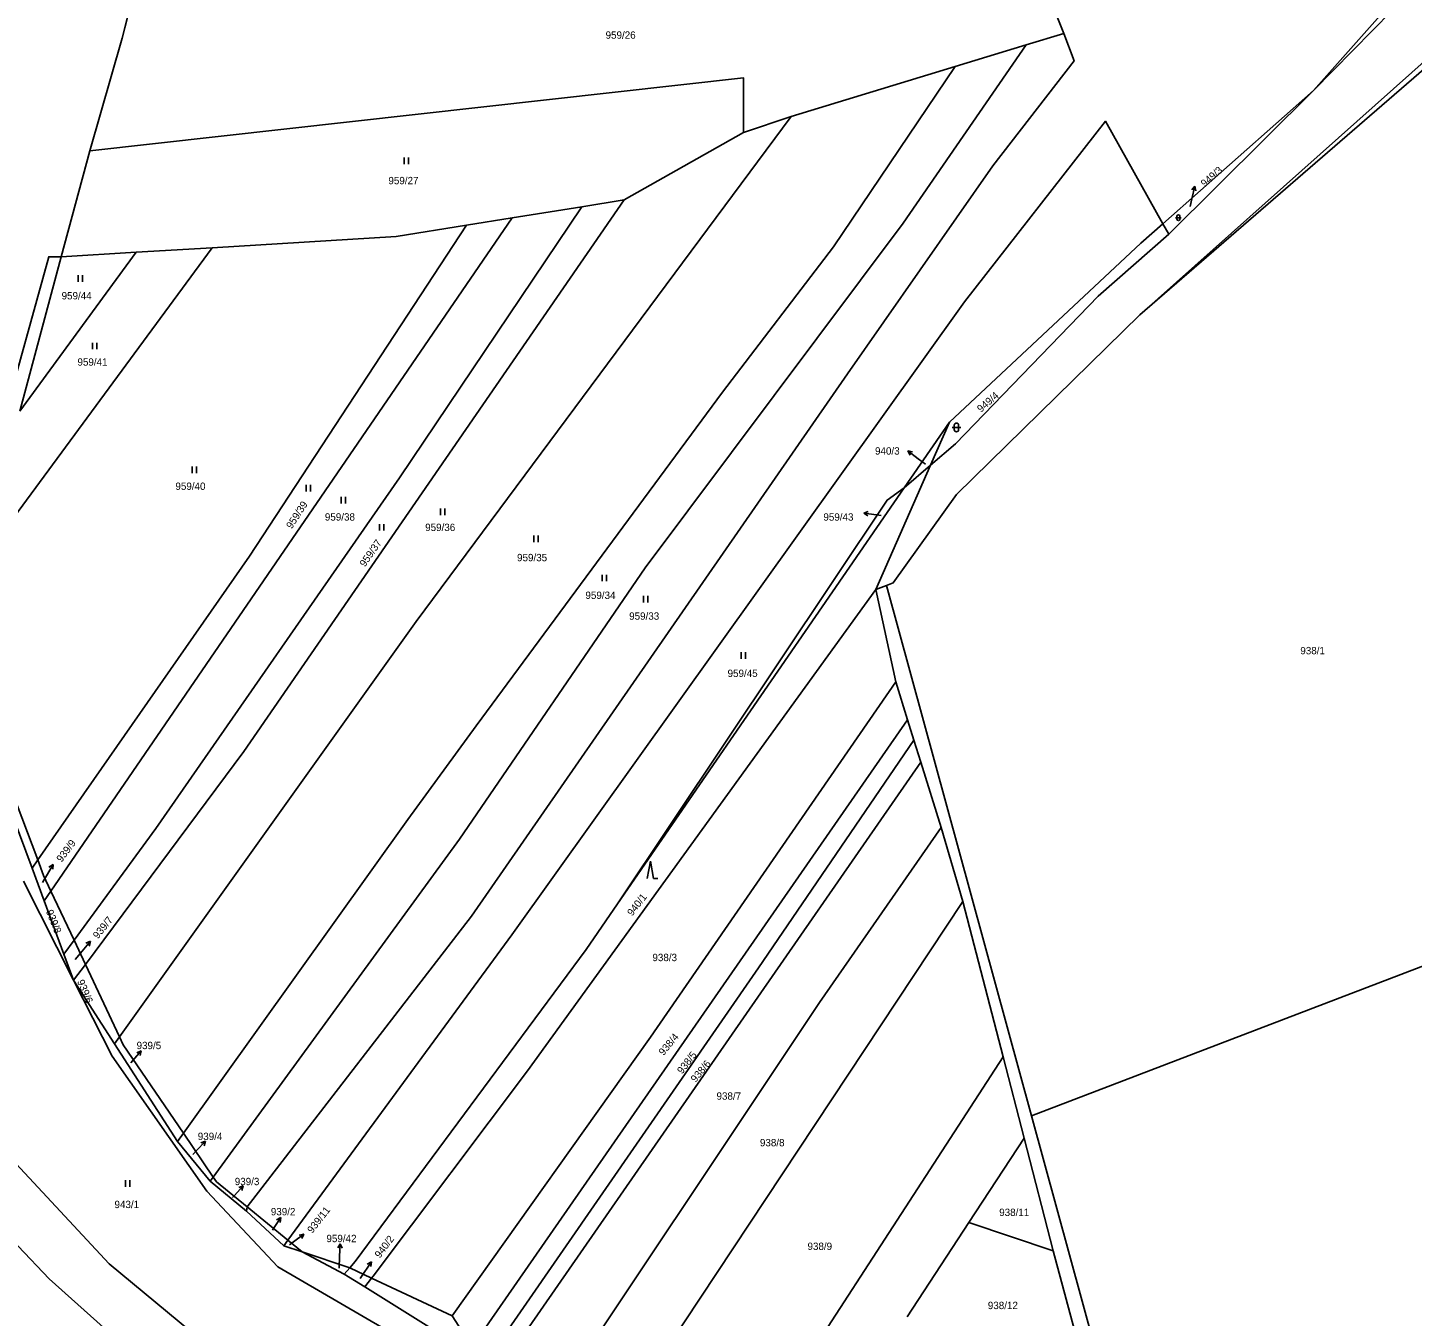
# Model space of a CAD drawing. Extents: x -757266 to -753360, y -1162585 to -1157740.
# Drawn here: x -756805.9 to -756485.7, y -1158661.2 to -1158363.2 of the extents above; entities that cross this region are included whole.
import ezdxf

# ---------------------------------------------------------------- set-up
doc = ezdxf.new("R2010")
doc.units = 0
for name, color, linetype in [('Hranice kat_území', 7, 'Continuous'), ('Hranice parcel', 7, 'Continuous'), ('Parcelní čísla', 7, 'Continuous'), ('Pop  PČ popisy', 7, 'Continuous'), ('Značky kultur', 7, 'Continuous')]:
    doc.layers.add(name, color=color, linetype=linetype)

msp = doc.modelspace()

# ---------------------------------------------------------------- linework, layer by layer
at = {"layer": 'Hranice kat_území'}
msp.add_lwpolyline([(-756781.24, -1158354.6), (-756784.03, -1158365.59), (-756791.53, -1158391.65), (-756798.13, -1158416.19), (-756801.03, -1158416.15), (-756811.68, -1158454.87), (-756825.92, -1158504.48), (-756835.2, -1158536), (-756846.27, -1158568.28), (-756847.94, -1158578.11), (-756854.12, -1158598.67), (-756855.85, -1158604.43), (-756860.92, -1158621.3), (-756876.64, -1158666.26), (-756892.84, -1158710.67), (-756909.75, -1158755.31), (-756929.5, -1158803.77), (-756945.9, -1158844.06)], dxfattribs=at)
at = {"layer": 'Hranice parcel'}
for p, q in [((-756566.33, -1158364.49), (-756578.91, -1158333.04)), ((-756548.7, -1158429.59), (-756447.67, -1158342.08)), ((-756781.24, -1158354.6), (-756784.03, -1158365.59)), ((-756491.3, -1158358.26), (-756508.58, -1158377.69)), ((-756490.34, -1158359.21), (-756508.58, -1158377.69)), ((-756574.98, -1158367.13), (-756566.33, -1158364.49)), ((-756784.03, -1158365.59), (-756791.53, -1158391.65)), ((-756591.46, -1158372.16), (-756574.98, -1158367.13)), ((-756629.34, -1158383.73), (-756591.46, -1158372.16)), ((-756508.58, -1158377.69), (-756543.38, -1158408.52)), ((-756508.58, -1158377.69), (-756542.03, -1158410.93)), ((-756640.34, -1158387.4), (-756629.34, -1158383.73)), ((-756667.96, -1158403.01), (-756640.34, -1158387.4)), ((-756791.53, -1158391.65), (-756798.13, -1158416.19)), ((-756677.78, -1158404.58), (-756667.96, -1158403.01)), ((-756693.84, -1158407.15), (-756677.78, -1158404.58)), ((-756704.46, -1158408.85), (-756693.84, -1158407.15)), ((-756543.38, -1158408.52), (-756542.03, -1158410.93)), ((-756763.27, -1158414.06), (-756817.31, -1158487.51)), ((-756780.81, -1158415.13), (-756807.73, -1158451.88)), ((-756807.73, -1158451.88), (-756798.13, -1158416.19)), ((-756798.13, -1158416.19), (-756801.03, -1158416.15)), ((-756798.13, -1158416.19), (-756780.81, -1158415.13)), ((-756780.81, -1158415.13), (-756763.27, -1158414.06)), ((-756592.73, -1158454.42), (-756603.18, -1158469.59)), ((-756597.1, -1158464.34), (-756592.73, -1158454.42)), ((-756609.77, -1158493.12), (-756597.1, -1158464.34)), ((-756597.1, -1158464.34), (-756603.18, -1158469.59)), ((-756603.18, -1158469.59), (-756669.5, -1158565.82)), ((-756607.32, -1158492.2), (-756609.77, -1158493.12)), ((-756605.18, -1158514.49), (-756609.77, -1158493.12)), ((-756607.32, -1158492.2), (-756573.78, -1158614.85)), ((-756602.46, -1158523.21), (-756605.18, -1158514.49)), ((-756703.1, -1158668.26), (-756602.46, -1158523.21)), ((-756600.97, -1158527.97), (-756602.46, -1158523.21)), ((-756599.39, -1158533.04), (-756600.97, -1158527.97)), ((-756698.31, -1158675.71), (-756599.39, -1158533.04)), ((-756594.68, -1158548.12), (-756599.39, -1158533.04)), ((-756589.63, -1158565.22), (-756594.68, -1158548.12)), ((-756803.58, -1158555.65), (-756804.89, -1158557.54)), ((-756573.78, -1158614.85), (-756418.09, -1158555.21)), ((-756795.26, -1158583.48), (-756806.89, -1158560.55)), ((-756804.89, -1158557.54), (-756802.08, -1158565.11)), ((-756800.53, -1158562.84), (-756802.08, -1158565.11)), ((-756795.17, -1158574.23), (-756800.53, -1158562.84)), ((-756802.08, -1158565.11), (-756797.51, -1158577.42)), ((-756682.2, -1158705.02), (-756589.63, -1158565.22)), ((-756580.35, -1158601.17), (-756589.63, -1158565.22)), ((-756795.17, -1158574.23), (-756797.51, -1158577.42)), ((-756792.54, -1158579.83), (-756795.17, -1158574.23)), ((-756797.51, -1158577.42), (-756795.26, -1158583.48)), ((-756792.54, -1158579.83), (-756795.26, -1158583.48)), ((-756784.66, -1158596.58), (-756792.54, -1158579.83)), ((-756785.82, -1158598.21), (-756795.26, -1158583.48)), ((-756784.66, -1158596.58), (-756785.82, -1158598.21)), ((-756771.23, -1158620.76), (-756785.82, -1158598.21)), ((-756575.49, -1158619.99), (-756580.35, -1158601.17)), ((-756543.91, -1158724.09), (-756573.78, -1158614.85)), ((-756769.87, -1158618.85), (-756771.23, -1158620.76)), ((-756763.66, -1158629.91), (-756771.23, -1158620.76)), ((-756762.98, -1158628.97), (-756769.87, -1158618.85)), ((-756588.24, -1158639.46), (-756575.49, -1158619.99)), ((-756568.76, -1158646.08), (-756575.49, -1158619.99)), ((-756762.98, -1158628.97), (-756763.66, -1158629.91)), ((-756755.3, -1158636.87), (-756763.66, -1158629.91)), ((-756755.11, -1158635.9), (-756755.3, -1158636.87)), ((-756746.69, -1158644.89), (-756755.3, -1158636.87)), ((-756745.73, -1158643.58), (-756755.11, -1158635.9)), ((-756602.54, -1158661.29), (-756588.24, -1158639.46)), ((-756588.24, -1158639.46), (-756568.76, -1158646.08)), ((-756746.69, -1158644.89), (-756745.73, -1158643.58)), ((-756742.41, -1158646.3), (-756745.73, -1158643.58)), ((-756742.41, -1158646.3), (-756746.69, -1158644.89)), ((-756731.41, -1158649.97), (-756742.41, -1158646.3)), ((-756742.41, -1158646.3), (-756732.68, -1158651.43)), ((-756559.23, -1158681.29), (-756568.76, -1158646.08)), ((-756731.41, -1158649.97), (-756732.68, -1158651.43)), ((-756731.41, -1158649.97), (-756726.36, -1158652.34)), ((-756732.68, -1158651.43), (-756727.91, -1158654.4)), ((-756727.91, -1158654.4), (-756726.36, -1158652.34)), ((-756707.71, -1158661.08), (-756726.36, -1158652.34)), ((-756703.1, -1158668.26), (-756707.71, -1158661.08))]:
    msp.add_line(p, q, dxfattribs=at)
for points in [[(-756447.67, -1158342.08), (-756448.37, -1158340.11), (-756548.7, -1158429.59)], [(-756566.33, -1158364.49), (-756563.9, -1158370.88), (-756582.68, -1158395.1), (-756616.3, -1158443.25)], [(-756574.98, -1158367.13), (-756603.41, -1158408.36), (-756663.1, -1158488.06), (-756706.06, -1158550.84), (-756762.98, -1158628.97)], [(-756791.53, -1158391.65), (-756640.34, -1158374.79), (-756640.34, -1158387.4)], [(-756591.46, -1158372.16), (-756619.59, -1158413.83), (-756645.25, -1158447.45), (-756702.2, -1158524.66), (-756717.99, -1158546.3), (-756769.87, -1158618.85)], [(-756629.34, -1158383.73), (-756716.04, -1158500.54), (-756784.66, -1158596.58)], [(-756745.73, -1158643.58), (-756693.91, -1158572.95), (-756589.28, -1158426.55), (-756556.65, -1158384.81), (-756543.38, -1158408.52)], [(-756667.96, -1158403.01), (-756755.93, -1158530.58), (-756792.54, -1158579.83)], [(-756677.78, -1158404.58), (-756719.91, -1158467.27), (-756776.27, -1158548.39), (-756795.17, -1158574.23)], [(-756704.46, -1158408.85), (-756754.58, -1158485.41), (-756803.58, -1158555.65)], [(-756693.84, -1158407.15), (-756732.41, -1158463.4), (-756800.53, -1158562.84)], [(-756763.27, -1158414.06), (-756720.72, -1158411.46), (-756704.46, -1158408.85)], [(-756543.38, -1158408.52), (-756548.5, -1158413.05), (-756592.73, -1158454.42)], [(-756542.03, -1158410.93), (-756558.36, -1158425.3), (-756591.36, -1158459.39), (-756597.1, -1158464.34)], [(-756801.03, -1158416.15), (-756811.68, -1158454.87), (-756825.92, -1158504.48), (-756835.2, -1158536)], [(-756548.7, -1158429.59), (-756591.1, -1158471.17), (-756605.74, -1158491.6), (-756607.32, -1158492.2)], [(-756616.3, -1158443.25), (-756703.28, -1158568.66), (-756755.11, -1158635.9)], [(-756603.18, -1158469.59), (-756607.15, -1158472.44), (-756669.5, -1158565.82)], [(-756726.36, -1158652.34), (-756726.04, -1158651.92), (-756690.28, -1158604.41), (-756648.3, -1158546.4), (-756609.77, -1158493.12)], [(-756820.94, -1158501.85), (-756821.89, -1158503.54), (-756820.99, -1158510.1), (-756822.73, -1158509.72), (-756804.89, -1158557.54)], [(-756803.58, -1158555.65), (-756812.24, -1158532.59), (-756819.92, -1158512.2), (-756820.94, -1158501.85)], [(-756707.71, -1158661.08), (-756661.91, -1158596.62), (-756605.18, -1158514.49)], [(-756700.41, -1158672.44), (-756636.9, -1158580.56), (-756600.97, -1158527.97)], [(-756689.77, -1158689.02), (-756622.77, -1158588.64), (-756594.68, -1158548.12)], [(-756800.53, -1158562.84), (-756802.24, -1158559.21), (-756803.58, -1158555.65)], [(-756669.5, -1158565.82), (-756676.78, -1158576.39), (-756730.13, -1158648.51), (-756731.41, -1158649.97)], [(-756712.37, -1158672.52), (-756713.76, -1158669.73), (-756748.02, -1158649.78), (-756764.47, -1158632.26), (-756786.37, -1158600.99), (-756795.26, -1158583.48)], [(-756670.96, -1158755.67), (-756686.13, -1158736.94), (-756696.64, -1158725.27), (-756713.94, -1158710.12), (-756748.83, -1158680.75), (-756787.06, -1158649.03), (-756808.66, -1158625.84), (-756835.58, -1158596.23), (-756844.34, -1158586.44)], [(-756704.1, -1158962.35), (-756694.65, -1158943.1), (-756668.85, -1158906.92), (-756664.23, -1158896.45), (-756658.19, -1158866.49), (-756660.27, -1158849.21), (-756665.64, -1158810.88), (-756675.54, -1158767.56), (-756690.59, -1158747.65), (-756703.99, -1158734.09), (-756739.28, -1158704.77), (-756778.11, -1158672.96), (-756800.91, -1158652.49), (-756808.06, -1158644.98), (-756837.14, -1158613.12), (-756852.08, -1158598.85), (-756854.12, -1158598.67)], [(-756769.87, -1158618.85), (-756783.81, -1158598.38), (-756784.66, -1158596.58)], [(-756668.48, -1158733.77), (-756649.15, -1158707.23), (-756580.35, -1158601.17)], [(-756755.11, -1158635.9), (-756762.24, -1158630.06), (-756762.98, -1158628.97)], [(-756727.91, -1158654.4), (-756709.44, -1158665.92), (-756666.01, -1158753.76), (-756648.09, -1158869.34)]]:
    msp.add_lwpolyline(points, dxfattribs=at)
at = {"layer": 'Pop  PČ popisy'}
for p, q in [((-756536.005, -1158399.826), (-756536.718, -1158400.689)), ((-756536.68, -1158402.75), (-756536.005, -1158399.826)), ((-756536.005, -1158399.826), (-756535.742, -1158400.914)), ((-756537.09, -1158404.56), (-756536.68, -1158402.75)), ((-756599.96, -1158462.86), (-756602.357, -1158461.054)), ((-756602.357, -1158461.054), (-756601.256, -1158461.257)), ((-756602.357, -1158461.054), (-756601.858, -1158462.057)), ((-756598.29, -1158464.11), (-756599.96, -1158462.86)), ((-756612.559, -1158475.474), (-756611.504, -1158475.099)), ((-756609.58, -1158475.84), (-756612.559, -1158475.474)), ((-756612.559, -1158475.474), (-756611.626, -1158476.093)), ((-756608.55, -1158475.96), (-756609.58, -1158475.84)), ((-756801.53, -1158559.29), (-756800.03, -1158556.691)), ((-756800.03, -1158556.691), (-756800.964, -1158557.308)), ((-756800.03, -1158556.691), (-756800.097, -1158557.809)), ((-756802.44, -1158560.85), (-756801.53, -1158559.29)), ((-756793.31, -1158576.76), (-756791.381, -1158574.461)), ((-756791.381, -1158574.461), (-756792.408, -1158574.906)), ((-756791.381, -1158574.461), (-756791.641, -1158575.55)), ((-756794.88, -1158578.65), (-756793.31, -1158576.76)), ((-756782.04, -1158602.56), (-756781.61, -1158602.06)), ((-756781.61, -1158602.06), (-756779.641, -1158599.795)), ((-756779.641, -1158599.795), (-756780.676, -1158600.222)), ((-756779.641, -1158599.795), (-756779.92, -1158600.879)), ((-756766.83, -1158622.87), (-756764.783, -1158620.675)), ((-756764.783, -1158620.675), (-756765.833, -1158621.066)), ((-756764.783, -1158620.675), (-756765.1, -1158621.749)), ((-756767.69, -1158623.78), (-756766.83, -1158622.87)), ((-756758.09, -1158633.21), (-756756.043, -1158631.015)), ((-756756.043, -1158631.015), (-756757.093, -1158631.406)), ((-756756.043, -1158631.015), (-756756.36, -1158632.089)), ((-756758.52, -1158633.68), (-756758.09, -1158633.21)), ((-756749.04, -1158640.85), (-756747.362, -1158638.362)), ((-756747.362, -1158638.362), (-756748.337, -1158638.912)), ((-756747.362, -1158638.362), (-756747.507, -1158639.472)), ((-756749.32, -1158641.27), (-756749.04, -1158640.85)), ((-756744.44, -1158643.98), (-756742.012, -1158642.216)), ((-756742.012, -1158642.216), (-756743.117, -1158642.4)), ((-756742.012, -1158642.216), (-756742.528, -1158643.21)), ((-756745.37, -1158644.65), (-756744.44, -1158643.98)), ((-756733.655, -1158644.391), (-756734.191, -1158645.374)), ((-756733.76, -1158647.39), (-756733.655, -1158644.391)), ((-756733.655, -1158644.391), (-756733.19, -1158645.409)), ((-756733.83, -1158650.09), (-756733.76, -1158647.39)), ((-756728.06, -1158651.07), (-756726.382, -1158648.582)), ((-756726.382, -1158648.582), (-756727.357, -1158649.132)), ((-756726.382, -1158648.582), (-756726.527, -1158649.692)), ((-756728.99, -1158652.44), (-756728.06, -1158651.07))]:
    msp.add_line(p, q, dxfattribs=at)
at = {"layer": 'Značky kultur'}
for p, q in [((-756718.841, -1158394.71), (-756718.841, -1158393.21)), ((-756717.84, -1158394.71), (-756717.84, -1158393.21)), ((-756540.135, -1158406.785), (-756540.135, -1158407.456)), ((-756539.465, -1158407.456), (-756539.465, -1158406.785)), ((-756540.471, -1158407.121), (-756539.129, -1158407.121)), ((-756794.201, -1158421.95), (-756794.201, -1158420.45)), ((-756793.2, -1158421.95), (-756793.2, -1158420.45)), ((-756790.921, -1158437.56), (-756790.921, -1158436.06)), ((-756789.92, -1158437.56), (-756789.92, -1158436.06)), ((-756592.121, -1158455.621), (-756590.119, -1158455.621)), ((-756591.621, -1158455.121), (-756591.621, -1158456.122)), ((-756590.619, -1158456.122), (-756590.619, -1158455.121)), ((-756767.881, -1158466.17), (-756767.881, -1158464.67)), ((-756766.88, -1158466.17), (-756766.88, -1158464.67)), ((-756741.461, -1158470.44), (-756741.461, -1158468.94)), ((-756740.46, -1158470.44), (-756740.46, -1158468.94)), ((-756733.421, -1158473.18), (-756733.421, -1158471.68)), ((-756732.42, -1158473.18), (-756732.42, -1158471.68)), ((-756710.441, -1158475.9), (-756710.441, -1158474.4)), ((-756709.44, -1158475.9), (-756709.44, -1158474.4)), ((-756724.541, -1158479.5), (-756724.541, -1158478)), ((-756723.54, -1158479.5), (-756723.54, -1158478)), ((-756688.871, -1158482.15), (-756688.871, -1158480.65)), ((-756687.87, -1158482.15), (-756687.87, -1158480.65)), ((-756673.081, -1158491.21), (-756673.081, -1158489.71)), ((-756672.08, -1158491.21), (-756672.08, -1158489.71)), ((-756663.501, -1158496.1), (-756663.501, -1158494.6)), ((-756662.5, -1158496.1), (-756662.5, -1158494.6)), ((-756640.941, -1158509.13), (-756640.941, -1158507.63)), ((-756639.94, -1158509.13), (-756639.94, -1158507.63)), ((-756661.91, -1158555.96), (-756662.66, -1158559.96)), ((-756661.16, -1158559.96), (-756661.91, -1158555.96)), ((-756661.16, -1158559.96), (-756660.164, -1158559.96)), ((-756783.271, -1158631.21), (-756783.271, -1158629.71)), ((-756782.27, -1158631.21), (-756782.27, -1158629.71))]:
    msp.add_line(p, q, dxfattribs=at)
for centre, radius, start, end in [((-756539.8, -1158406.7856), 0.335, 0, 180), ((-756539.8, -1158407.4556), 0.335, 180, 359.987886), ((-756591.12, -1158455.1209), 0.5, 0, 180), ((-756591.12, -1158456.1209), 0.5, 180, 359.987886)]:
    msp.add_arc(centre, radius, start, end, dxfattribs=at)

# ---------------------------------------------------------------- texts
at = {"layer": 'Parcelní čísla'}
for s, p in [('959/26', (-756672.26, -1158365.74)), ('959/27', (-756722.48, -1158399.39)), ('959/44', (-756798.05, -1158426.02)), ('959/41', (-756794.38, -1158441.35)), ('940/3', (-756609.957, -1158461.91)), ('959/40', (-756771.73, -1158470.07)), ('959/38', (-756737.17, -1158477.17)), ('959/43', (-756621.895, -1158477.19)), ('959/36', (-756713.98, -1158479.59)), ('959/35', (-756692.73, -1158486.57)), ('959/34', (-756676.92, -1158495.29)), ('959/33', (-756666.81, -1158500.1)), ('938/1', (-756511.61, -1158508.09)), ('959/45', (-756644.05, -1158513.34)), ('938/3', (-756661.43, -1158579.05)), ('939/5', (-756780.71, -1158599.4)), ('938/7', (-756646.61, -1158611.1)), ('939/4', (-756766.56, -1158620.42)), ('938/8', (-756636.57, -1158621.87)), ('939/3', (-756758.01, -1158630.86)), ('943/1', (-756785.818, -1158636.16)), ('939/2', (-756749.67, -1158637.83)), ('938/11', (-756581.24, -1158637.99)), ('959/42', (-756736.81, -1158644.04)), ('938/9', (-756625.57, -1158645.84)), ('938/12', (-756583.87, -1158659.52))]:
    msp.add_text(s, height=1.7, dxfattribs=at).set_placement(p)
for s, rotation, p in [('949/3', 41, (-756533.732, -1158400.131)), ('949/4', 41, (-756585.462, -1158452.251)), ('959/39', 57, (-756744.837, -1158479.222)), ('959/37', 55, (-756727.903, -1158488.007)), ('939/9', 53, (-756798.051, -1158556.311)), ('940/1', 52, (-756666.1, -1158568.743)), ('939/8', 292, (-756801.708, -1158567.558)), ('939/7', 51, (-756789.659, -1158574.024)), ('939/6', 293, (-756794.502, -1158583.752)), ('938/4', 50, (-756658.868, -1158600.996)), ('938/5', 52, (-756654.55, -1158605.273)), ('938/6', 50, (-756651.458, -1158607.216)), ('939/11', 52, (-756740.08, -1158642.123)), ('940/2', 53, (-756724.461, -1158647.861))]:
    msp.add_text(s, height=1.7, rotation=rotation, dxfattribs=at).set_placement(p)

doc.saveas('drawing.dxf')
